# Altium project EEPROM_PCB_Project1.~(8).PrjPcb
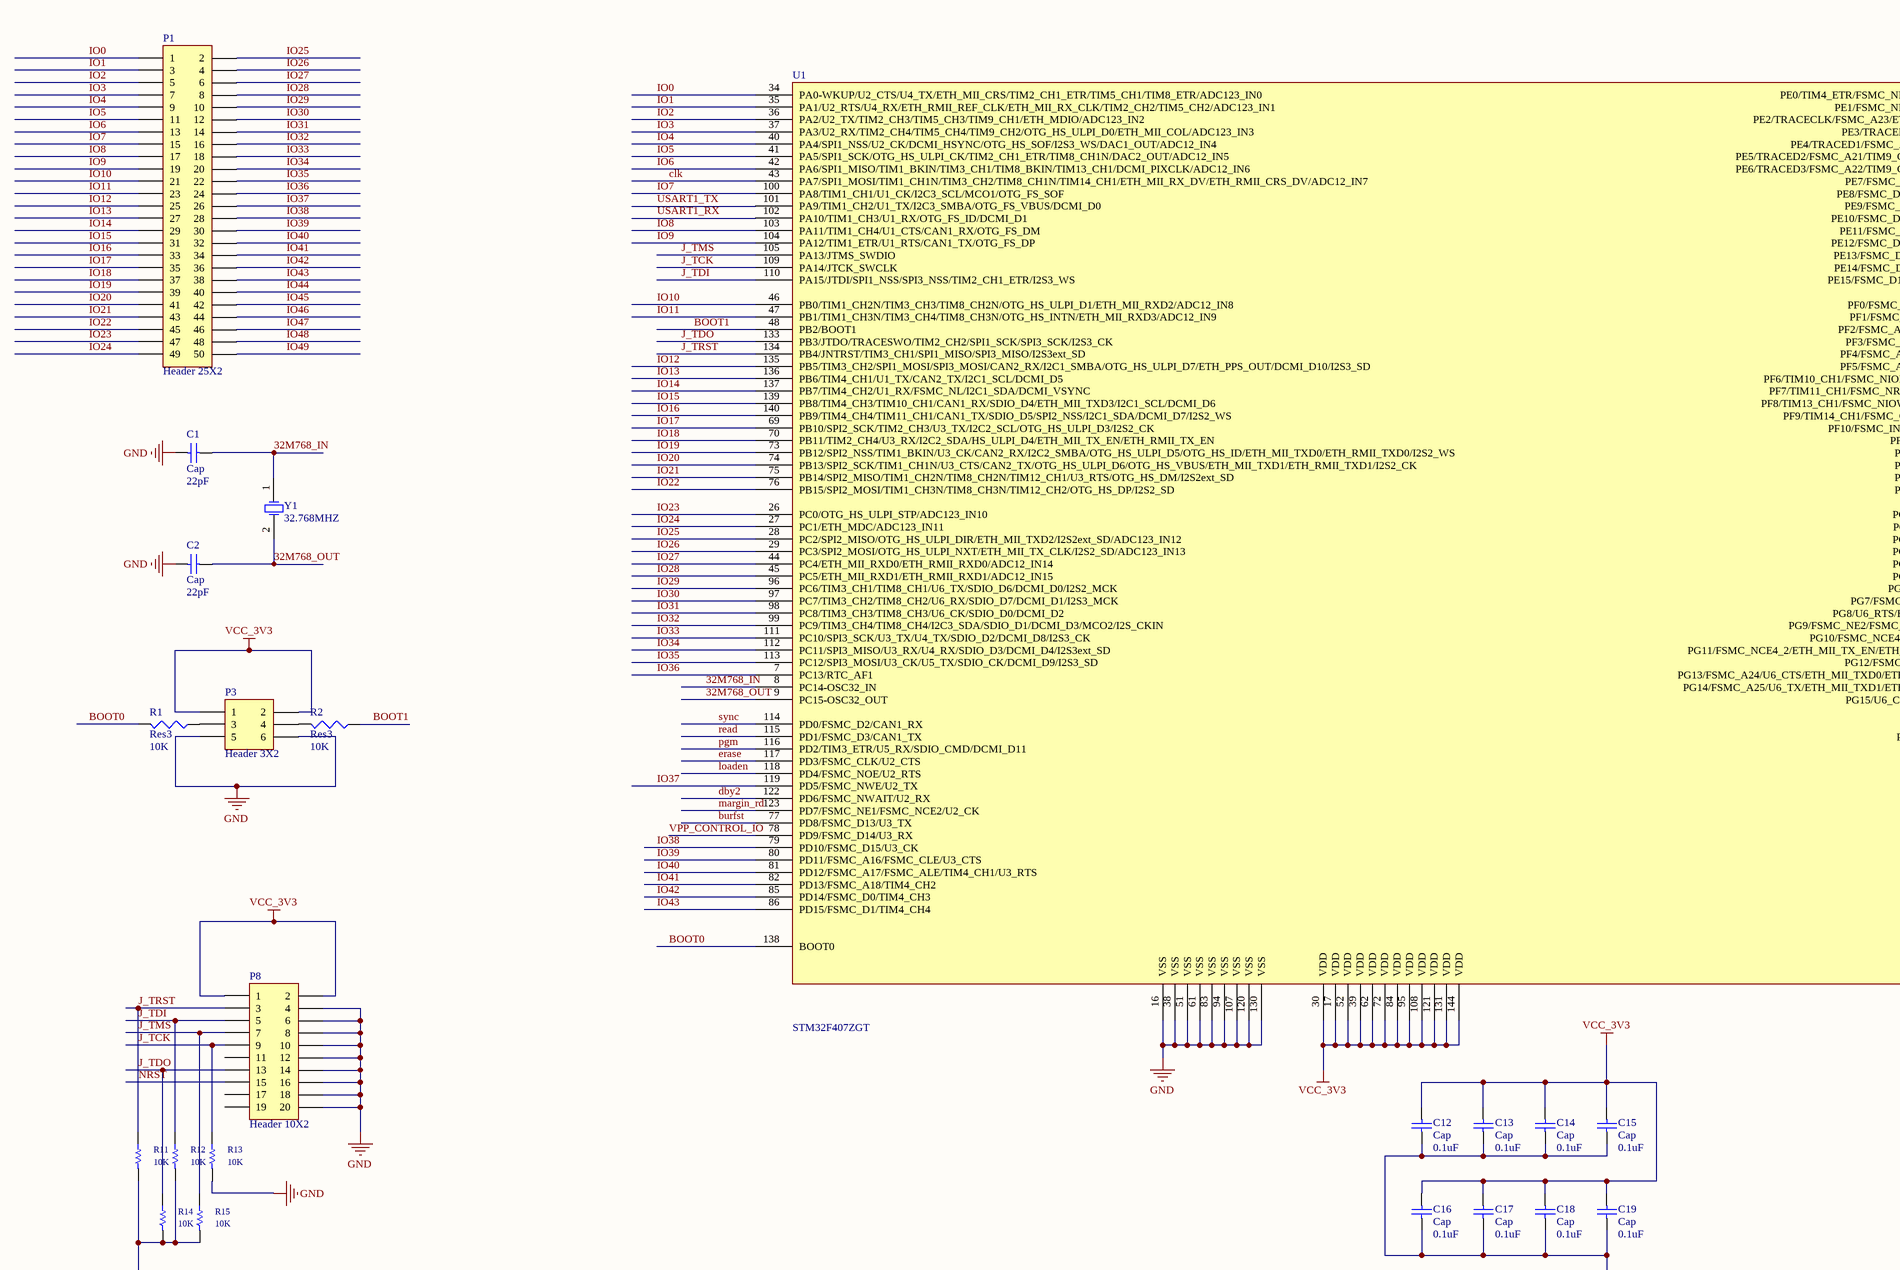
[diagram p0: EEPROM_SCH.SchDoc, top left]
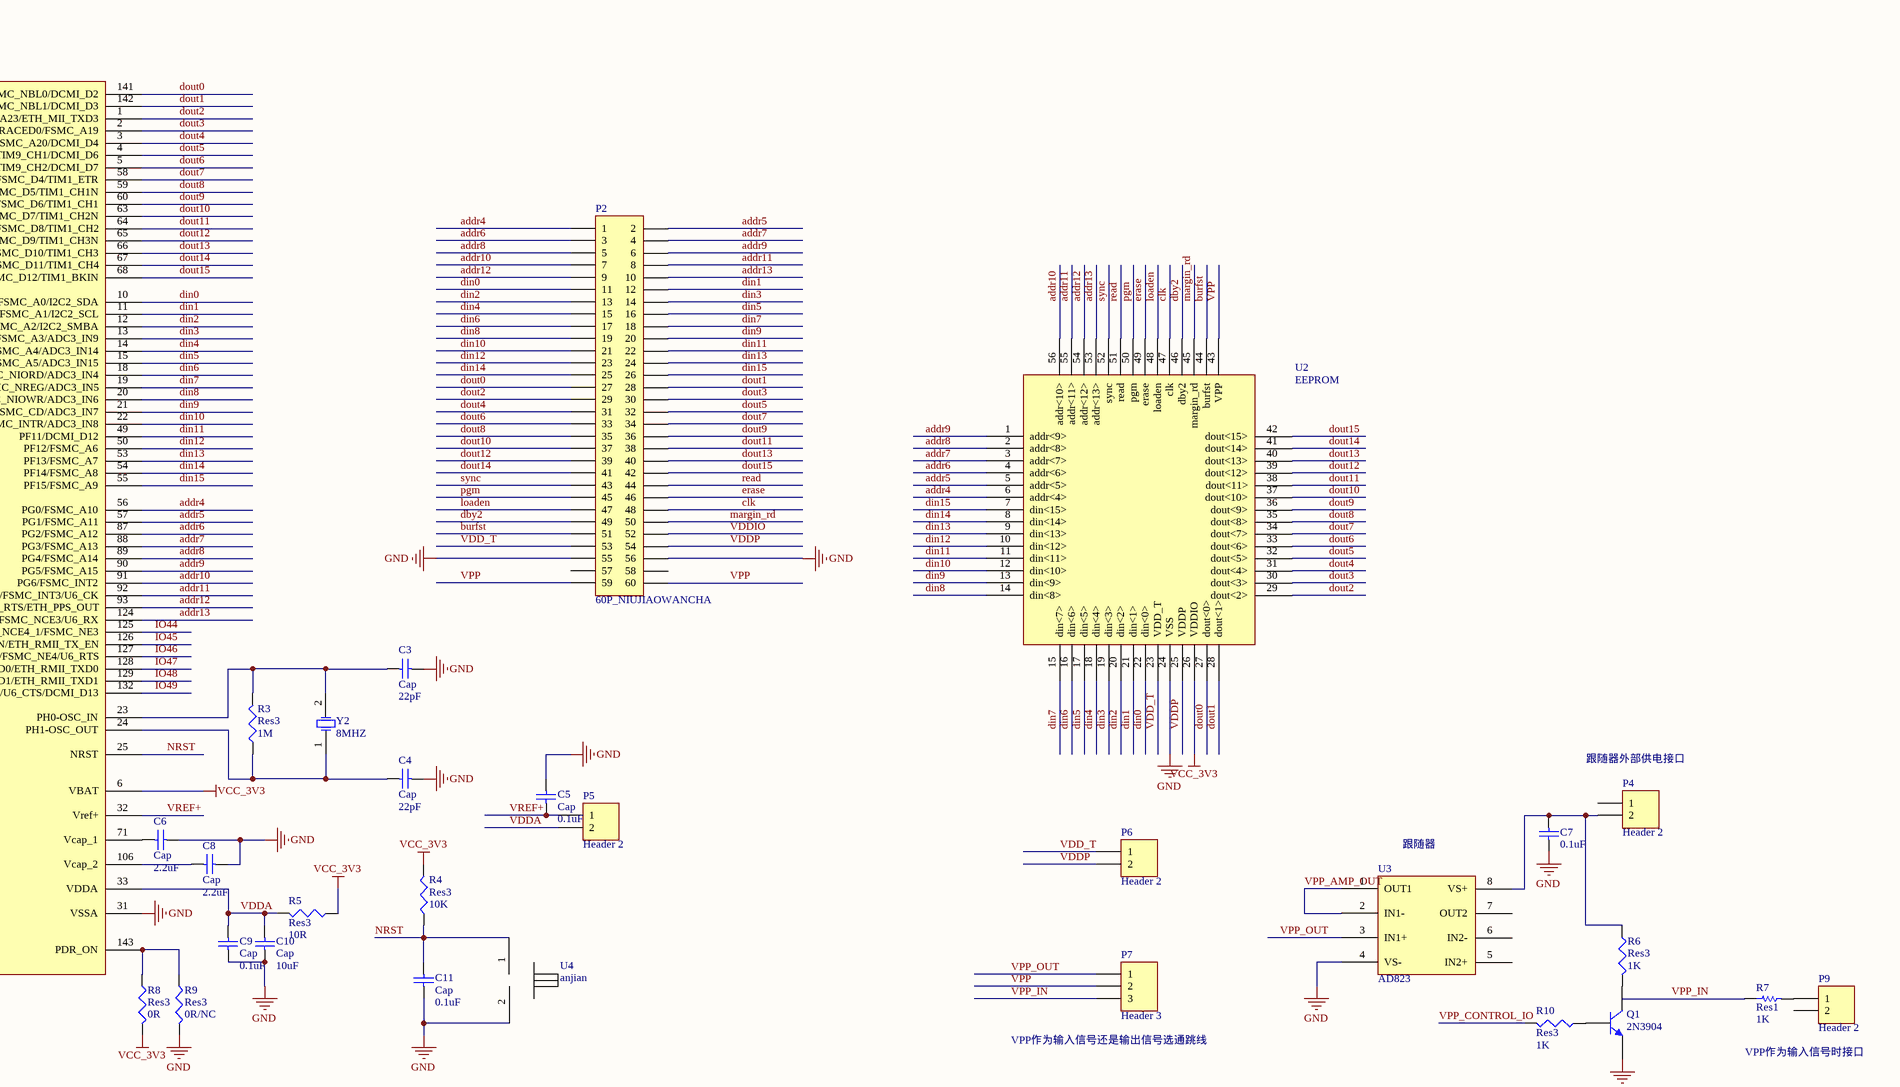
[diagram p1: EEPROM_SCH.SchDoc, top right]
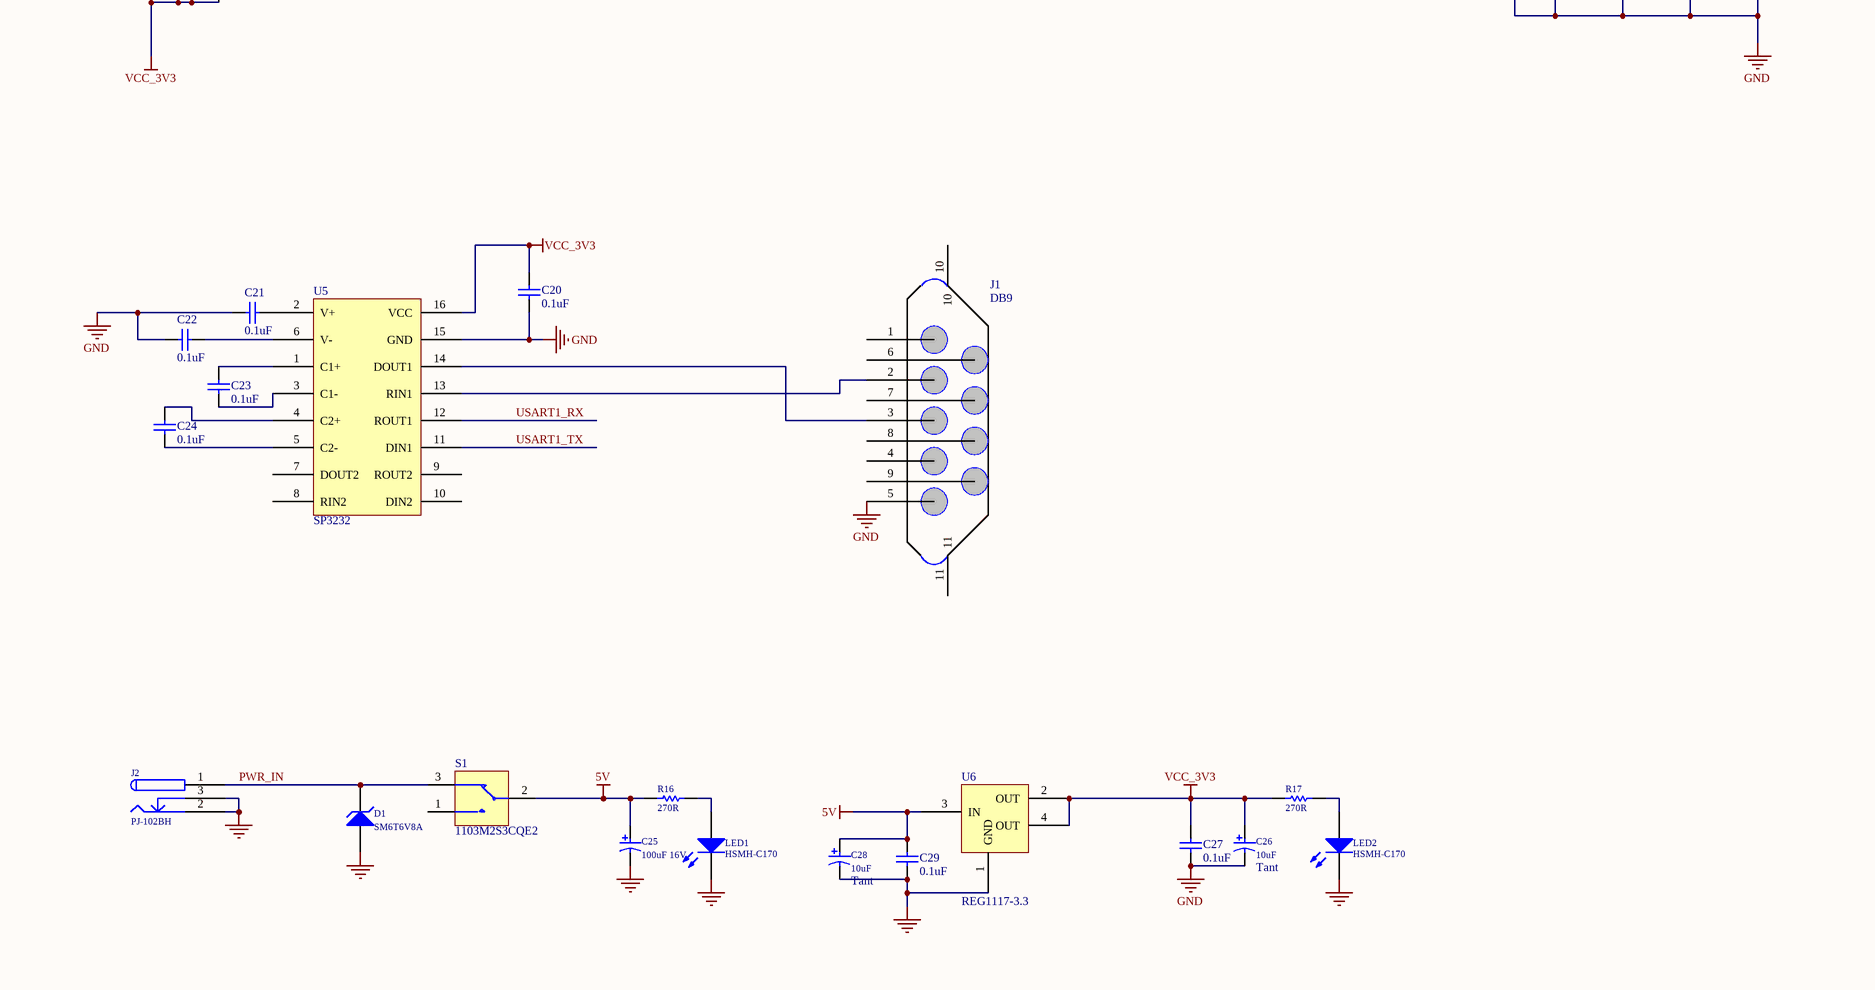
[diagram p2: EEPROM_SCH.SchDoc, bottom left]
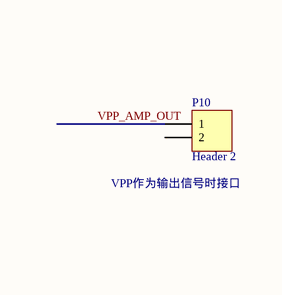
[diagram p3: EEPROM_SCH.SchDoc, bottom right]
1 sheet, 71 parts. Net scope: global (net labels, ports and power ports of the same name join across sheets).
Board file: stm32_PCB.PcbDoc

## Sheet EEPROM_SCH.SchDoc
size D

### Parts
C1  Cap  value 22pF  [RAD-0.3]
C2  Cap  value 22pF  [RAD-0.3]
C3  Cap  value 22pF  [RAD-0.3]
C4  Cap  value 22pF  [RAD-0.3]
C5  Cap  value 0.1uF  [RAD-0.3]
C6  Cap  value 2.2uF  [RAD-0.3]
C7  0.1uF  [CC2012-0805]
C8  Cap  value 2.2uF  [RAD-0.3]
C9  Cap  value 0.1uF  [RAD-0.3]
C10  Cap  value 10uF  [RAD-0.3]
C11  Cap  value 0.1uF  [RAD-0.3]
C12  Cap  value 0.1uF  [RAD-0.3]
C13  Cap  value 0.1uF  [RAD-0.3]
C14  Cap  value 0.1uF  [RAD-0.3]
C15  Cap  value 0.1uF  [RAD-0.3]
C16  Cap  value 0.1uF  [RAD-0.3]
C17  Cap  value 0.1uF  [RAD-0.3]
C18  Cap  value 0.1uF  [RAD-0.3]
C19  Cap  value 0.1uF  [RAD-0.3]
C20  0.1uF  [CC2012-0805]
C21  0.1uF  [CC2012-0805]
C22  0.1uF  [CC2012-0805]
C23  0.1uF  [CC2012-0805]
C24  0.1uF  [CC2012-0805]
C25  100uF 16V  [CAPPR2-5X6.8]
C26  10uF  Capacitor Type: Tant  [MCCT-B]
C27  0.1uF  [CC2012-0805]
C28  10uF  Capacitor Type: Tant  [MCCT-B]
C29  0.1uF  [CC2012-0805]
D1  SM6T6V8A  [PCBComponent_1]
J1  DB9  [PCBComponent_1]
J2  PJ-102BH  [PCBComponent_1]
LED1  HSMH-C170  [SMD _LED]
LED2  HSMH-C170  [SMD _LED]
P1  Header 25X2  [HDR2X25]
P2  60P_NIUJIAOWANCHA  [PCBComponent_1]
P3  Header 3X2  [PCBComponent_1]
P4  Header 2  [HDR1X2]
P5  Header 2  [HDR1X2]
P6  Header 2  [HDR1X2]
P7  Header 3  [HDR1X3]
P8  Header 10X2  [HDR2X10]
P9  Header 2  [HDR1X2]
P10  Header 2  [HDR1X2]
Q1  2N3904  [TO-92A]
R1  Res3  value 10K  [J1-0603]
R2  Res3  value 10K  [J1-0603]
R3  Res3  value 1M  [J1-0603]
R4  Res3  value 10K  [J1-0603]
R5  Res3  value 10R  [J1-0603]
R6  Res3  value 1K  [J1-0603]
R7  Res1  value 1K  [AXIAL-0.3]
R8  Res3  value 0R  [J1-0603]
R9  Res3  value 0R/NC  [J1-0603]
R10  Res3  value 1K  [J1-0603]
R11  10K  [CC2012-0805]
R12  10K  [CC2012-0805]
R13  10K  [CC2012-0805]
R14  10K  [CC2012-0805]
R15  10K  [CC2012-0805]
R16  270R  [CR2012-0805]
R17  270R  [CR2012-0805]
S1  1103M2S3CQE2  [PCBComponent_1]
U1  STM32F407ZGT  [STM32F407ZGT6_LCC144]
U2  EEPROM
U3  AD823  [PCBComponent_1]
U4  anjian
U5  SP3232
U6  REG1117-3.3  [PCBComponent_1]
Y1  32.768MHZ  [PCBComponent_1]
Y2  8MHZ  [PCBComponent_1]

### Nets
5V: C25.1 C28.1 C29.2 R16.2 S1.2 U6.3(IN)
GND: C1.1 C2.1 C3.1 C4.1 C5.1 C6.2 C7.1 C8.2 C9.2 C10.2 C11.2 C12.1 C13.1 C14.1 C15.1 C16.1 C17.1 C18.1 C19.1 C20.1 C21.1 C22.2 C25.2 C26.2 C27.1 C28.2 C29.1 D1.1(A) J1.5 J2.2 J2.3 LED1.2(K) LED2.2(K) P2.55 P2.56 P3.5 P3.6 P8.4 P8.6 P8.8 P8.10 P8.12 P8.14 P8.16 P8.18 P8.20 Q1.1(E) R9.2 R13.2 U1.16(VSS) U1.31(VSSA) U1.38(VSS) U1.51(VSS) U1.61(VSS) U1.83(VSS) U1.94(VSS) U1.107(VSS) U1.120(VSS) U1.130(VSS) U2.24(VSS) U3.4(VS-) U4.2 U5.15(GND) U6.1(GND)
VCC_3V3: C12.2 C13.2 C14.2 C15.2 C16.2 C17.2 C18.2 C19.2 C20.2 C26.1 C27.2 P3.1 P3.2 P8.1 P8.2 R4.2 R5.1 R8.2 R11.2 R12.2 R14.2 R15.2 R17.2 U1.6(VBAT) U1.17(VDD) U1.30(VDD) U1.39(VDD) U1.52(VDD) U1.62(VDD) U1.72(VDD) U1.84(VDD) U1.95(VDD) U1.108(VDD) U1.121(VDD) U1.131(VDD) U1.144(VDD) U2.26(VDDIO) U5.16(VCC) U6.2(OUT) U6.4(OUT)
32M768_IN: C1.2 U1.8(PC14-OSC32_IN) Y1.1(OSC1)
32M768_OUT: C2.2 U1.9(PC15-OSC32_OUT) Y1.2(OSC2)
addr4: P2.1 U1.56(PG0/FSMC_A10) U2.6(addr<4>)
addr5: P2.2 U1.57(PG1/FSMC_A11) U2.5(addr<5>)
addr6: P2.3 U1.87(PG2/FSMC_A12) U2.4(addr<6>)
addr7: P2.4 U1.88(PG3/FSMC_A13) U2.3(addr<7>)
addr8: P2.5 U1.89(PG4/FSMC_A14) U2.2(addr<8>)
addr9: P2.6 U1.90(PG5/FSMC_A15) U2.1(addr<9>)
addr10: P2.7 U1.91(PG6/FSMC_INT2) U2.56(addr<10>)
addr11: P2.8 U1.92(PG7/FSMC_INT3/U6_CK) U2.55(addr<11>)
addr12: P2.9 U1.93(PG8/U6_RTS/ETH_PPS_OUT) U2.54(addr<12>)
addr13: P2.10 U1.124(PG9/FSMC_NE2/FSMC_NCE3/U6_RX) U2.53(addr<13>)
BOOT0: R1.2 U1.138(BOOT0)
BOOT1: R2.1 U1.48(PB2/BOOT1)
burfst: P2.51 U1.77(PD8/FSMC_D13/U3_TX) U2.44(burfst)
clk: P2.48 U1.43(PA7/SPI1_MOSI/TIM1_CH1N/TIM3_CH2/TIM8_CH1N/TIM14_CH1/ETH_MII_RX_DV/ETH_RMII_CRS_DV/ADC12_IN7) U2.47(clk)
dby2: P2.49 U1.122(PD6/FSMC_NWAIT/U2_RX) U2.46(dby2)
din0: P2.11 U1.10(PF0/FSMC_A0/I2C2_SDA) U2.22(din<0>)
din1: P2.12 U1.11(PF1/FSMC_A1/I2C2_SCL) U2.21(din<1>)
din2: P2.13 U1.12(PF2/FSMC_A2/I2C2_SMBA) U2.20(din<2>)
din3: P2.14 U1.13(PF3/FSMC_A3/ADC3_IN9) U2.19(din<3>)
din4: P2.15 U1.14(PF4/FSMC_A4/ADC3_IN14) U2.18(din<4>)
din5: P2.16 U1.15(PF5/FSMC_A5/ADC3_IN15) U2.17(din<5>)
din6: P2.17 U1.18(PF6/TIM10_CH1/FSMC_NIORD/ADC3_IN4) U2.16(din<6>)
din7: P2.18 U1.19(PF7/TIM11_CH1/FSMC_NREG/ADC3_IN5) U2.15(din<7>)
din8: P2.19 U1.20(PF8/TIM13_CH1/FSMC_NIOWR/ADC3_IN6) U2.14(din<8>)
din9: P2.20 U1.21(PF9/TIM14_CH1/FSMC_CD/ADC3_IN7) U2.13(din<9>)
din10: P2.21 U1.22(PF10/FSMC_INTR/ADC3_IN8) U2.12(din<10>)
din11: P2.22 U1.49(PF11/DCMI_D12) U2.11(din<11>)
din12: P2.23 U1.50(PF12/FSMC_A6) U2.10(din<12>)
din13: P2.24 U1.53(PF13/FSMC_A7) U2.9(din<13>)
din14: P2.25 U1.54(PF14/FSMC_A8) U2.8(din<14>)
din15: P2.26 U1.55(PF15/FSMC_A9) U2.7(din<15>)
dout0: P2.27 U1.141(PE0/TIM4_ETR/FSMC_NBL0/DCMI_D2) U2.27(dout<0>)
dout1: P2.28 U1.142(PE1/FSMC_NBL1/DCMI_D3) U2.28(dout<1>)
dout2: P2.29 U1.1(PE2/TRACECLK/FSMC_A23/ETH_MII_TXD3) U2.29(dout<2>)
dout3: P2.30 U1.2(PE3/TRACED0/FSMC_A19) U2.30(dout<3>)
dout4: P2.31 U1.3(PE4/TRACED1/FSMC_A20/DCMI_D4) U2.31(dout<4>)
dout5: P2.32 U1.4(PE5/TRACED2/FSMC_A21/TIM9_CH1/DCMI_D6) U2.32(dout<5>)
dout6: P2.33 U1.5(PE6/TRACED3/FSMC_A22/TIM9_CH2/DCMI_D7) U2.33(dout<6>)
dout7: P2.34 U1.58(PE7/FSMC_D4/TIM1_ETR) U2.34(dout<7>)
dout8: P2.35 U1.59(PE8/FSMC_D5/TIM1_CH1N) U2.35(dout<8>)
dout9: P2.36 U1.60(PE9/FSMC_D6/TIM1_CH1) U2.36(dout<9>)
dout10: P2.37 U1.63(PE10/FSMC_D7/TIM1_CH2N) U2.37(dout<10>)
dout11: P2.38 U1.64(PE11/FSMC_D8/TIM1_CH2) U2.38(dout<11>)
dout12: P2.39 U1.65(PE12/FSMC_D9/TIM1_CH3N) U2.39(dout<12>)
dout13: P2.40 U1.66(PE13/FSMC_D10/TIM1_CH3) U2.40(dout<13>)
dout14: P2.41 U1.67(PE14/FSMC_D11/TIM1_CH4) U2.41(dout<14>)
dout15: P2.42 U1.68(PE15/FSMC_D12/TIM1_BKIN) U2.42(dout<15>)
erase: P2.46 U1.117(PD3/FSMC_CLK/U2_CTS) U2.49(erase)
IO0: P1.1 U1.34(PA0-WKUP/U2_CTS/U4_TX/ETH_MII_CRS/TIM2_CH1_ETR/TIM5_CH1/TIM8_ETR/ADC123_IN0)
IO1: P1.3 U1.35(PA1/U2_RTS/U4_RX/ETH_RMII_REF_CLK/ETH_MII_RX_CLK/TIM2_CH2/TIM5_CH2/ADC123_IN1)
IO2: P1.5 U1.36(PA2/U2_TX/TIM2_CH3/TIM5_CH3/TIM9_CH1/ETH_MDIO/ADC123_IN2)
IO3: P1.7 U1.37(PA3/U2_RX/TIM2_CH4/TIM5_CH4/TIM9_CH2/OTG_HS_ULPI_D0/ETH_MII_COL/ADC123_IN3)
IO4: P1.9 U1.40(PA4/SPI1_NSS/U2_CK/DCMI_HSYNC/OTG_HS_SOF/I2S3_WS/DAC1_OUT/ADC12_IN4)
IO5: P1.11 U1.41(PA5/SPI1_SCK/OTG_HS_ULPI_CK/TIM2_CH1_ETR/TIM8_CH1N/DAC2_OUT/ADC12_IN5)
IO6: P1.13 U1.42(PA6/SPI1_MISO/TIM1_BKIN/TIM3_CH1/TIM8_BKIN/TIM13_CH1/DCMI_PIXCLK/ADC12_IN6)
IO7: P1.15 U1.100(PA8/TIM1_CH1/U1_CK/I2C3_SCL/MCO1/OTG_FS_SOF)
IO8: P1.17 U1.103(PA11/TIM1_CH4/U1_CTS/CAN1_RX/OTG_FS_DM)
IO9: P1.19 U1.104(PA12/TIM1_ETR/U1_RTS/CAN1_TX/OTG_FS_DP)
IO10: P1.21 U1.46(PB0/TIM1_CH2N/TIM3_CH3/TIM8_CH2N/OTG_HS_ULPI_D1/ETH_MII_RXD2/ADC12_IN8)
IO11: P1.23 U1.47(PB1/TIM1_CH3N/TIM3_CH4/TIM8_CH3N/OTG_HS_INTN/ETH_MII_RXD3/ADC12_IN9)
IO12: P1.25 U1.135(PB5/TIM3_CH2/SPI1_MOSI/SPI3_MOSI/CAN2_RX/I2C1_SMBA/OTG_HS_ULPI_D7/ETH_PPS_OUT/DCMI_D10/I2S3_SD)
IO13: P1.27 U1.136(PB6/TIM4_CH1/U1_TX/CAN2_TX/I2C1_SCL/DCMI_D5)
IO14: P1.29 U1.137(PB7/TIM4_CH2/U1_RX/FSMC_NL/I2C1_SDA/DCMI_VSYNC)
IO15: P1.31 U1.139(PB8/TIM4_CH3/TIM10_CH1/CAN1_RX/SDIO_D4/ETH_MII_TXD3/I2C1_SCL/DCMI_D6)
IO16: P1.33 U1.140(PB9/TIM4_CH4/TIM11_CH1/CAN1_TX/SDIO_D5/SPI2_NSS/I2C1_SDA/DCMI_D7/I2S2_WS)
IO17: P1.35 U1.69(PB10/SPI2_SCK/TIM2_CH3/U3_TX/I2C2_SCL/OTG_HS_ULPI_D3/I2S2_CK)
IO18: P1.37 U1.70(PB11/TIM2_CH4/U3_RX/I2C2_SDA/HS_ULPI_D4/ETH_MII_TX_EN/ETH_RMII_TX_EN)
IO19: P1.39 U1.73(PB12/SPI2_NSS/TIM1_BKIN/U3_CK/CAN2_RX/I2C2_SMBA/OTG_HS_ULPI_D5/OTG_HS_ID/ETH_MII_TXD0/ETH_RMII_TXD0/I2S2_WS)
IO20: P1.41 U1.74(PB13/SPI2_SCK/TIM1_CH1N/U3_CTS/CAN2_TX/OTG_HS_ULPI_D6/OTG_HS_VBUS/ETH_MII_TXD1/ETH_RMII_TXD1/I2S2_CK)
IO21: P1.43 U1.75(PB14/SPI2_MISO/TIM1_CH2N/TIM8_CH2N/TIM12_CH1/U3_RTS/OTG_HS_DM/I2S2ext_SD)
IO22: P1.45 U1.76(PB15/SPI2_MOSI/TIM1_CH3N/TIM8_CH3N/TIM12_CH2/OTG_HS_DP/I2S2_SD)
IO23: P1.47 U1.26(PC0/OTG_HS_ULPI_STP/ADC123_IN10)
IO24: P1.49 U1.27(PC1/ETH_MDC/ADC123_IN11)
IO25: P1.2 U1.28(PC2/SPI2_MISO/OTG_HS_ULPI_DIR/ETH_MII_TXD2/I2S2ext_SD/ADC123_IN12)
IO26: P1.4 U1.29(PC3/SPI2_MOSI/OTG_HS_ULPI_NXT/ETH_MII_TX_CLK/I2S2_SD/ADC123_IN13)
IO27: P1.6 U1.44(PC4/ETH_MII_RXD0/ETH_RMII_RXD0/ADC12_IN14)
IO28: P1.8 U1.45(PC5/ETH_MII_RXD1/ETH_RMII_RXD1/ADC12_IN15)
IO29: P1.10 U1.96(PC6/TIM3_CH1/TIM8_CH1/U6_TX/SDIO_D6/DCMI_D0/I2S2_MCK)
IO30: P1.12 U1.97(PC7/TIM3_CH2/TIM8_CH2/U6_RX/SDIO_D7/DCMI_D1/I2S3_MCK)
IO31: P1.14 U1.98(PC8/TIM3_CH3/TIM8_CH3/U6_CK/SDIO_D0/DCMI_D2)
IO32: P1.16 U1.99(PC9/TIM3_CH4/TIM8_CH4/I2C3_SDA/SDIO_D1/DCMI_D3/MCO2/I2S_CKIN)
IO33: P1.18 U1.111(PC10/SPI3_SCK/U3_TX/U4_TX/SDIO_D2/DCMI_D8/I2S3_CK)
IO34: P1.20 U1.112(PC11/SPI3_MISO/U3_RX/U4_RX/SDIO_D3/DCMI_D4/I2S3ext_SD)
IO35: P1.22 U1.113(PC12/SPI3_MOSI/U3_CK/U5_TX/SDIO_CK/DCMI_D9/I2S3_SD)
IO36: P1.24 U1.7(PC13/RTC_AF1)
IO37: P1.26 U1.119(PD5/FSMC_NWE/U2_TX)
IO38: P1.28 U1.79(PD10/FSMC_D15/U3_CK)
IO39: P1.30 U1.80(PD11/FSMC_A16/FSMC_CLE/U3_CTS)
IO40: P1.32 U1.81(PD12/FSMC_A17/FSMC_ALE/TIM4_CH1/U3_RTS)
IO41: P1.34 U1.82(PD13/FSMC_A18/TIM4_CH2)
IO42: P1.36 U1.85(PD14/FSMC_D0/TIM4_CH3)
IO43: P1.38 U1.86(PD15/FSMC_D1/TIM4_CH4)
IO44: P1.40 U1.125(PG10/FSMC_NCE4_1/FSMC_NE3)
IO45: P1.42 U1.126(PG11/FSMC_NCE4_2/ETH_MII_TX_EN/ETH_RMII_TX_EN)
IO46: P1.44 U1.127(PG12/FSMC_NE4/U6_RTS)
IO47: P1.46 U1.128(PG13/FSMC_A24/U6_CTS/ETH_MII_TXD0/ETH_RMII_TXD0)
IO48: P1.48 U1.129(PG14/FSMC_A25/U6_TX/ETH_MII_TXD1/ETH_RMII_TXD1)
IO49: P1.50 U1.132(PG15/U6_CTS/DCMI_D13)
J_TCK: C11.1 P8.3 P8.5 P8.7 P8.9 P8.13 P8.15 R4.1 R11.1 R12.1 R13.1 R14.1 R15.1 U1.25(NRST) U1.105(PA13/JTMS_SWDIO) U1.109(PA14/JTCK_SWCLK) U1.110(PA15/JTDI/SPI1_NSS/SPI3_NSS/TIM2_CH1_ETR/I2S3_WS) U1.133(PB3/JTDO/TRACESWO/TIM2_CH2/SPI1_SCK/SPI3_SCK/I2S3_CK) U1.134(PB4/JNTRST/TIM3_CH1/SPI1_MISO/SPI3_MISO/I2S3ext_SD) U4.1  [also labelled J_TDI, J_TDO, J_TMS, J_TRST, NRST]
loaden: P2.47 U1.118(PD4/FSMC_NOE/U2_RTS) U2.48(loaden)
margin_rd: P2.50 U1.123(PD7/FSMC_NE1/FSMC_NCE2/U2_CK) U2.45(margin_rd)
pgm: P2.45 U1.116(PD2/TIM3_ETR/U5_RX/SDIO_CMD/DCMI_D11) U2.50(pgm)
PWR_IN: D1.2(K) J2.1 S1.3
read: P2.44 U1.115(PD1/FSMC_D3/CAN1_TX) U2.51(read)
sync: P2.43 U1.114(PD0/FSMC_D2/CAN1_RX) U2.52(sync)
USART1_RX: U1.102(PA10/TIM1_CH3/U1_RX/OTG_FS_ID/DCMI_D1) U5.12(ROUT1)
USART1_TX: U1.101(PA9/TIM1_CH2/U1_TX/I2C3_SMBA/OTG_FS_VBUS/DCMI_D0) U5.11(DIN1)
VDD_T: P2.53 P6.1 U2.23(VDD_T)
VDDA: C9.1 C10.1 P5.2 R5.2 U1.33(VDDA)
VDDIO: P2.52
VDDP: P2.54 P6.2 U2.25(VDDP)
VPP: P2.59 P2.60 P7.2 U2.43(VPP)
VPP_AMP_OUT: P10.1 U3.1(OUT1) U3.2(IN1-)
VPP_CONTROL_IO: R10.2 U1.78(PD9/FSMC_D14/U3_RX)
VPP_IN: P7.3 R7.1
VPP_OUT: P7.1 U3.3(IN1+)
VREF+: C5.2 P5.1 U1.32(Vref+)
NetC3_2: C3.2 R3.2 U1.23(PH0-OSC_IN) Y2.2(OSC2)
NetC4_2: C4.2 R3.1 U1.24(PH1-OSC_OUT) Y2.1(OSC1)
NetC6_1: C6.1 U1.71(Vcap_1)
NetC7_2: C7.2 P4.2 R6.1 U3.8(VS+)
NetC8_1: C8.1 U1.106(Vcap_2)
NetC21_2: C21.2 U5.2(V+)
NetC22_1: C22.1 U5.6(V-)
NetC23_1: C23.1 U5.3(C1-)
NetC23_2: C23.2 U5.1(C1+)
NetC24_1: C24.1 U5.5(C2-)
NetC24_2: C24.2 U5.4(C2+)
NetJ1_2: J1.2 U5.13(RIN1)
NetJ1_3: J1.3 U5.14(DOUT1)
NetLED1_1: LED1.1(A) R16.1
NetLED2_1: LED2.1(A) R17.1
NetP3_3: P3.3 R1.1
NetP3_4: P3.4 R2.2
NetP9_1: P9.1 R7.2
NetQ1_2: Q1.2(B) R10.1
NetQ1_3: Q1.3(C) R6.2
NetR8_1: R8.1 R9.1 U1.143(PDR_ON)

Not connected (* = marked no-connect by the designer): J1 1 4 6 7 8 9 10 11; P2 57 58; P4 1; P8 11 17 19; P9 2; P10 2; S1 1; U3 5(IN2+) 6(IN2-) 7(OUT2); U5 7(DOUT2) 8(RIN2) 9(ROUT2) 10(DIN2)

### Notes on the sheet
- (near P4) 跟随器外部供电接口
- (near U3) 跟随器
- (near P7) VPP作为输入信号还是输出信号选通跳线
- VPP作为输入信号时接口
- (near P10) VPP作为输出信号时接口

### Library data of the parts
C1-C6 C8-C19 = Cap: Capacitor
C7 C20-C24 C27 C29 = CAP: Capacitor
C25 = CAP_POLAR_1: Polar Capacitor
C26 C28 = CAP_POLAR: Polar Capacitor; AEMS Code: 2100110
D1 = BZG03C13: Zener Diode, 6.2V, 5W; Manufacturer: Microsemi
J1 U1-U6 = Component_1
J2 = KLD-0202-B: Low Voltage Power Supply Connector; Manufacturer: Kycon; AEMS Code: 3510211
LED1 LED2 = HSMX-C670: Typical RED GaAs SMD LED Agilent make; AEMS Code: 2610081
P1 = Header 25X2: Header, 25-Pin, Dual row
P2 = Header 30X2: Header, 30-Pin, Dual row
P3 = Header 3X2: Header, 3-Pin, Dual row
P4-P6 P9 P10 = Header 2: Header, 2-Pin
P7 = Header 3: Header, 3-Pin
P8 = Header 10X2: Header, 10-Pin, Dual row
Q1 = 2N3904: NPN General Purpose Amplifier
R1-R6 R8-R10 = Res3: Resistor
R7 = Res1: Resistor
R11-R15 = RES: Resistor; AEMS Code: 1200012JT
R16 R17 = RES: Resistor; AEMS Code: 1200430
S1 = PCB_MOUNT_SWITCH: SPDT Subminiature Toggle Switch
Y1 Y2 = XTAL: Crystal Oscillator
